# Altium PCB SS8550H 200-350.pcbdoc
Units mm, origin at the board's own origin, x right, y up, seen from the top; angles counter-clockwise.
Board outline 15.62 x 14.95 mm, 2 copper layers (Top Layer, Bottom Layer), stack 0 mm thick; 1 components, 0 nets, 3 pads, 0 vias.
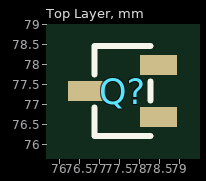
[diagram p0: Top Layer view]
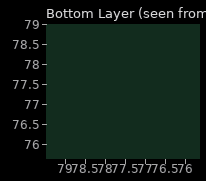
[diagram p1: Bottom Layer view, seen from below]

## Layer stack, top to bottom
Top Layer: signal copper (thickness not stored)
Bottom Layer: signal copper (thickness not stored)

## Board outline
85.466,69.85 69.85,69.85 69.85,84.802 85.466,84.802

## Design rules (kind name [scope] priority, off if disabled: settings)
PasteMaskExpansion "Paste Mask Expansion" [All] p1: expansion=0
SolderMaskExpansion "Solder Mask Expansion" [IsVia] p1: expansion=-25.4 istentingtop=TRUE
SolderMaskExpansion "Solder Mask Expansion" [All] p2: expansion=0.051 istentingtop=FALSE

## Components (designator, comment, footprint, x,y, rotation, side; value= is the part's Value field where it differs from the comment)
Q? "SS8550(RANGE:200-350)" SOT-323-3_L2.0-W1.3-P1.30-LS2.1-BR 77.566,77.326 r0 top

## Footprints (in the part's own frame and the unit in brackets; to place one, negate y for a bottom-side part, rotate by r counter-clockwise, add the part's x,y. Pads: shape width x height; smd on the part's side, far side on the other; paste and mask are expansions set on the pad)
SOT-323-3_L2.0-W1.3-P1.30-LS2.1-BR [mm]
  rect 0.936x0.5 smd: 1(0.898,-0.65) 2(0.898,0.65) 3(-0.898,0)
  silkscreen extent -0.7,-1.13 0.7,1.13

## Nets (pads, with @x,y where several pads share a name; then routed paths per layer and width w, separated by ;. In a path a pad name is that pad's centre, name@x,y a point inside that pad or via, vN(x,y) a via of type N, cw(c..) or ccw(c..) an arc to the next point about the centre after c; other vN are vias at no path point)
pads on no net: Q?.1 Q?.2 Q?.3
